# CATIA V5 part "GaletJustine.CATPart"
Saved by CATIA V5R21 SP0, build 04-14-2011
Part number: GaletJustine
Bounding box of the stored display mesh (mm): x 0 to 11, y -8.955 to 31.045, z -16.273 to 49.927
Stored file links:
  C:\Users\2027.DESARCY-LEMIE30\Desktop\Assemblage26.05\GaletJustine.CATPart
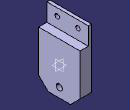
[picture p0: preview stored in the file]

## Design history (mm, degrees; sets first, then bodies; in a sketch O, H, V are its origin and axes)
Body1 (main body)
  Sketch1 on yz-plane, origin (0, 0, 0), H (0, 1, 0), V (0, 0, 1)
    line L1 (0.2374, -16.2729) -> (21.8526, -16.2729)
    line L2 (21.8526, -16.2729) -> (31.045, -7.0805)
    point P3 (31.045, -7.0805)
    line L3 (0.2374, -16.2729) -> (-8.955, -7.0805)
    line L4 (-8.955, -7.0805) -> (-8.955, 49.9271)
    line L5 (31.045, -7.0805) -> (31.045, 49.9271)
    point P6 (31.045, -7.0805)
    line L6 (-8.955, 49.9271) -> (31.045, 49.9271)
    circle A1 centre (11.045, -7.2729) radius 3
    point P8 (11.045, -7.2729)
    length L3 = 13
    angle L1 L3 = 45
    length L2 = 13
    distance L1 L6 = 66.2
    length L6 = 40
    radius A1 = 3
    distance P8 L5 = 20
    distance P8 L1 = 9
    horizontal: L1 H, L6 H
    perpendicularity: L3 L2
    vertical: L4 V, L5 V
    coincidence: P6 L2, P3 P6
  Pad1: profile Sketch1, direction (1, 0, 0), length 11
  Sketch2 on end face of Pad1, origin (11, 0, 0), H (0, 1, 0), V (0, 0, 1)
    line L1 (-8.955, 49.9271) -> (31.045, 49.9271)
    line L2 (31.045, 49.9271) -> (31.045, 32.9271)
    line L3 (-8.955, 49.9271) -> (-8.955, 32.9271)
    line L4 (-8.955, 32.9271) -> (31.045, 32.9271)
    reference projected line E1 (31.045, 49.9271) -> (-8.955, 49.9271) from edge [face of Pad1 from Sketch1.L6 | end face of Pad1]
    reference projected line E2 (31.045, -7.0805) -> (31.045, 49.9271) from edge [face of Pad1 from Sketch1.L5 | end face of Pad1]
    reference projected line E3 (-8.955, 49.9271) -> (-8.955, -7.0805) from edge [face of Pad1 from Sketch1.L4 | end face of Pad1]
    length L3 = 17
    horizontal: L1 H, L4 H
    vertical: L2 V, L3 V
    coincidence: L1 E1, L2 E2, L3 E3
  Pocket1: profile Sketch2, direction (-1, 0, 0), length 8
  Sketch3 on end face of Pocket1, origin (3, 0, 0), H (0, 1, 0), V (0, 0, 1)
    circle A1 centre (1.045, 42.9271) radius 2.25
    point P1 (1.045, 42.9271)
    circle A2 centre (21.045, 42.9271) radius 2.25
    point P2 (21.045, 42.9271)
    reference projected line E1 (-8.955, 49.9271) -> (-8.955, 32.9271) from edge [face of Pad1 from Sketch1.L4 | end face of Pocket1]
    reference projected line E2 (-8.955, 32.9271) -> (31.045, 32.9271) from edge [end face of Pad1 | face of Pocket1 from Sketch2.L4]
    reference projected line E3 (-8.955, 32.9271) -> (31.045, 32.9271) from edge [end face of Pad1 | face of Pocket1 from Sketch2.L4]
    reference projected line E4 (31.045, 32.9271) -> (31.045, 49.9271) from edge [face of Pad1 from Sketch1.L5 | end face of Pocket1]
    radius A1 = 2.25
    radius A2 = 2.25
    distance P1 E1 = 10
    distance P1 E2 = 10
    distance P2 E3 = 10
    distance P2 E4 = 10
  Pocket2: profile Sketch3, direction (-1, 0, 0), length 3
